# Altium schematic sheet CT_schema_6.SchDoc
size 278 x 170 mm
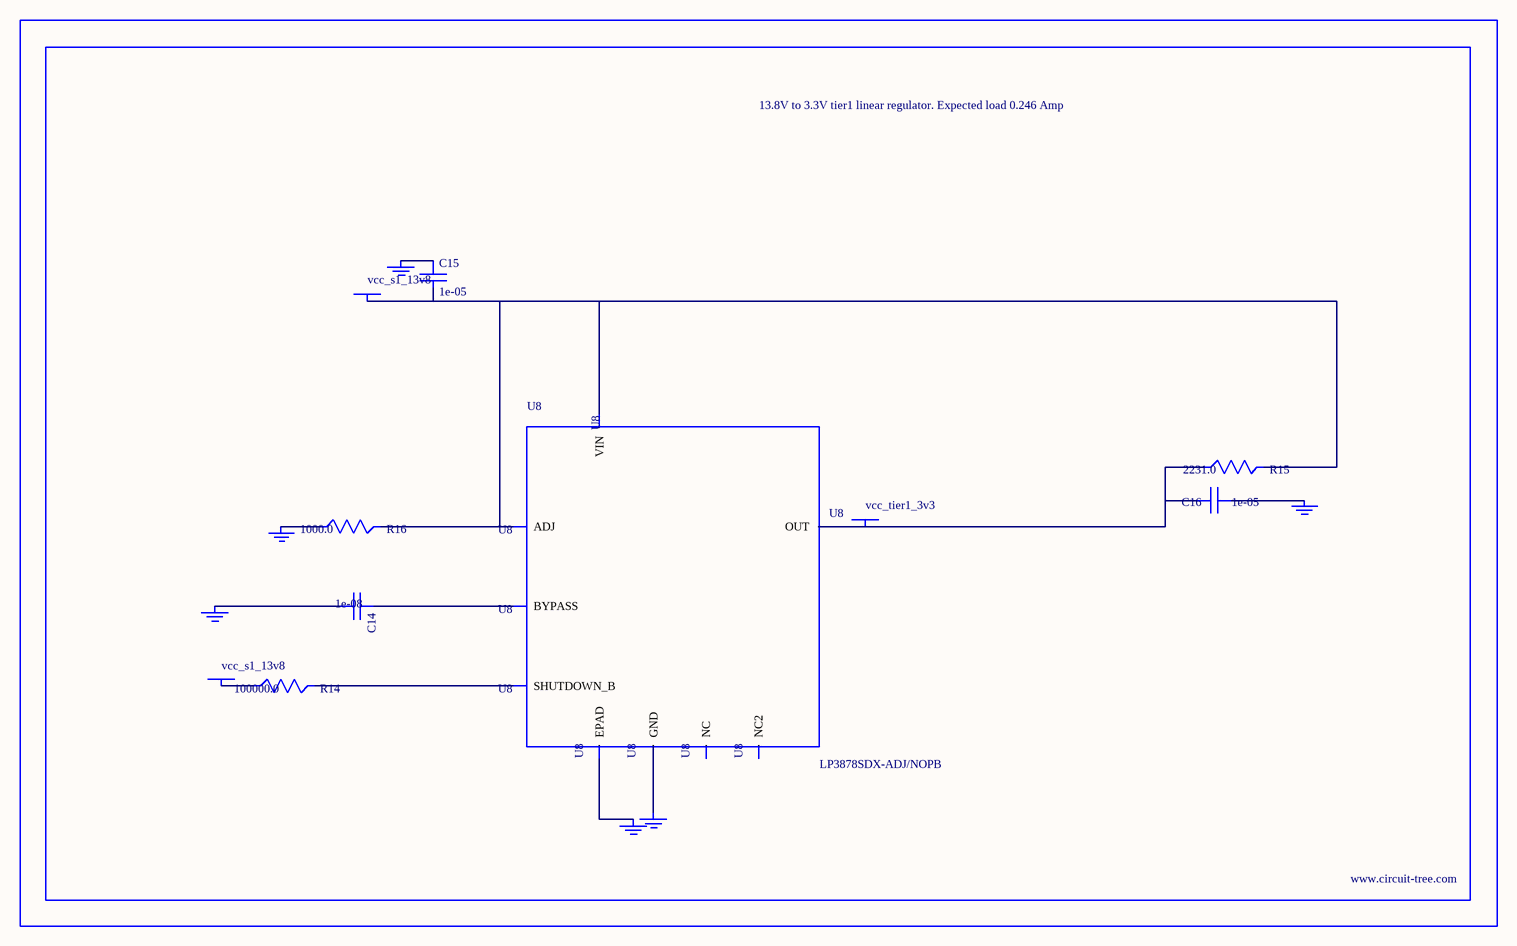
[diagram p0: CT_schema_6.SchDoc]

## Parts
BORDER5  (no value)
C14  1e-08  [C0402]
C15  1e-05  [C1210]
C16  1e-05  [C1210]
GND_INSTANCE_5_0  (no value)
GND_INSTANCE_5_1  (no value)
GND_INSTANCE_5_2  (no value)
GND_INSTANCE_5_3  (no value)
GND_INSTANCE_5_4  (no value)
GND_INSTANCE_5_5  (no value)
POWER_INSTANCE_5_0  vcc_s1_13v8
POWER_INSTANCE_5_1  vcc_s1_13v8
POWER_INSTANCE_5_2  vcc_tier1_3v3
R14  100000.0  [R0603]
R15  2231.0  [R0603]
R16  1000.0  [R0603]
U8  LP3878SDX-ADJ/NOPB  [WSON-8]

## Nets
NetC14_1: C14.1 U8.1(BYPASS)
NetC14_2: C14.2 GND_INSTANCE_5_0.0(GND)
NetC15_1: C15.1 GND_INSTANCE_5_1.0(GND)
NetC15_2: C15.2 POWER_INSTANCE_5_0.0(PWR) R15.2 R16.2 U8.4(VIN) U8.6(ADJ)
NetC16_1: C16.1 GND_INSTANCE_5_2.0(GND)
NetC16_2: C16.2 POWER_INSTANCE_5_2.0(PWR) R15.1 U8.5(OUT)
NetGND_INSTANCE_5_3_0: GND_INSTANCE_5_3.0(GND) R16.1
NetGND_INSTANCE_5_4_0: GND_INSTANCE_5_4.0(GND) U8.PAD(EPAD)
NetGND_INSTANCE_5_5_0: GND_INSTANCE_5_5.0(GND) U8.3(GND)
NetPOWER_INSTANCE_5_1_0: POWER_INSTANCE_5_1.0(PWR) R14.1
NetR14_2: R14.2 U8.8(SHUTDOWN_B)

Not connected (* = marked no-connect by the designer): U8 2(NC) 7(NC2)

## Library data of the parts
BORDER5 = BORDER_PAGE5
C14 = C0402C103K3RAC
C15 = C1210C106K5PACTU
C16 = GRM32DR61E106MA12L
GND_INSTANCE_5_0-GND_INSTANCE_5_5 = GND
POWER_INSTANCE_5_0-POWER_INSTANCE_5_2 = PWR
R14 = RC0603JR-07100KL
R15 = R15
R16 = RC0603JR-071KL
